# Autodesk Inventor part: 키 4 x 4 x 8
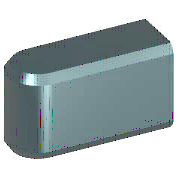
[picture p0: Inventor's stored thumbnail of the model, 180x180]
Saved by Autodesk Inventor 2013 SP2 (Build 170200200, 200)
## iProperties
Created: 2012-02
Part Number: 키 4 x 4 x 8
Material: 강철, 연강
Description: 키 및 해당 키홈
Document SubType Name: Modeling
Standard: KS B 1311
Designer: mduedu
Standards Organization: KS
Language: ko-KR
Size Designation: 4 x 4 x 8
Categories: <MemberInstance><Categories><Category DisplayName="샤프트 부품" InternalName="7f7aeb1f-a693-4053-b835-cee3144e0d98" Mnemonic="SHFT"><Category DisplayName="키" Interna
Density: 7.86 g/cm^3
Mass: 2.19103 g
Surface Area: 2.9828 cm^2
Volume: 0.278756 cm^3
IsCustomPart: 1
Author: mduedu
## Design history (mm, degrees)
sketch "스케치1"
  geometry: L1 (2, 2)-(18, 2); L2 (18, 2)-(18, -2); L3 (18, -2)-(2, -2); L4 (0, 2.8)-(0, -2.8) reference; L5 (-1.6, 0)-(9.6, 0) reference; A1 r 2 centre (2, 0) between (2, 2) and (2, -2)
  constraints: 6 end point, 3 tangent, 2 point on circle, 1 centre point, 1 horizontal, 1 parallel, 1 perpendicular, 1 point on line
  dimensions: "d0" = 2 radius of A1 (= 0.5 x PB); "d7" = 18 distance between parallel lines of L2 L4 (= NLG)
workplane "Work Plane1"
workplane "Work Plane2"
extrude "본체1" new body sketch "스케치1" taper "d3" = 0 deg; stored distance "d4" = 10
workaxis "Work Axis1"
workplane "Work Plane4"
body "Solid1"
chamfer "모따기1" distance "d8" = 0.25 (= PHH); stored, may be unused: second distance "d9" = 0.25 (= PHH), angle "d13" = 45 deg
other parameters: "d1" = -2.5 (= -PNT), "d2" = 1.5 (= PH - PNT), "NLG" = 18 [user parameter; used in 2 equation terms], "PB" = 4 [user parameter; used in 1 equation term], "PNT" = 2.5 [user parameter; used in 2 equation terms], "PH" = 4 [user parameter; used in 1 equation term], "PHH" = 0.25 [user parameter; used in 2 equation terms], "d10" = 0, "d16" = 0, "d17" = 0, "d18" = 0, "RR" = 0.08 [user parameter], "WDMAX" = 12 [user parameter], "PLB1" = 18 (= NLG) [user parameter], "PUEB" = 1.8 [user parameter]
